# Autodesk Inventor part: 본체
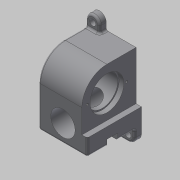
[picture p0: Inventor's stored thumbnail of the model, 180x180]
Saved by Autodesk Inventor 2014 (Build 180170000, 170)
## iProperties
Created: 2019-06
Part Number: 본체
Material: 알루미늄 6061
Document SubType Name: Modeling
Designer: mduedu
Density: 1 g/cm^3
Appearance: 기본값
Author: mduedu
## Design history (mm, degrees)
sketch "스케치1"
  geometry: L1 (37, 0)-(37, -43); L2 (37, -43)-(-60, -43); L3 (-60, -43)-(-60, 37); L4 (-60, 37)-(0, 37); A1 r 37 centre (0, 0) between (37, 0) and (0, 37); 1 further point
  constraints: 8 end point, 2 point on circle, 2 tangent, 1 centre point, 1 coincident, 1 horizontal, 1 parallel, 1 perpendicular, 1 vertical
  dimensions: "d0" = 37 radius of A1; "d2" = 80 distance of L2.end L3.end; "d3" = 97 distance of L1.end L2.end
extrude "돌출1" new body sketch "스케치1" stored distance "d4" = 72; taper "d5" = 0 deg
sketch "스케치2"
  geometry: L1 (72, 25)-(64, 25); L2 (64, 25)-(64, 97); L3 (64, 97)-(72, 97); L4 (72, 97)-(72, 25); L5 (72, 97)-(0, 97) reference; L6 (72, 60)-(72, 0) reference; 1 further point
  constraints: 8 end point, 2 collinear, 2 parallel, 1 horizontal, 1 perpendicular
  dimensions: "d6" = 72 distance between parallel lines of L1 L3; "d8" = 8 distance of L1.start L1.end
extrude "돌출2" cut sketch "스케치2" stored distance "d9" = 72; taper "d10" = 0 deg
sketch "스케치3"
  geometry: L1 (-36, -60)-(-36, 37) reference; L2 (-36, 37)-(28, 37) reference; L3 (28, 37)-(28, -35) reference; L4 (28, -35)-(36, -35) reference; L5 (36, -35)-(36, -60) reference; L6 (36, -60)-(-36, -60) reference; L7 (-36, 0)-(-19, 0); L8 (-19, 0)-(-19, 17.5); L9 (-19, 17.5)-(-36, 17.5); L10 (-36, 17.5)-(-36, 0); L11 (-19, 0)-(21, 0); L12 (21, 0)-(21, 23); L13 (21, 23)-(-19, 23); L14 (-19, 23)-(-19, 0); L15 (21, 0)-(28, 0); L16 (28, 0)-(28, 25); L17 (28, 25)-(21, 25); L18 (21, 25)-(21, 0); 1 further point
  constraints: 24 end point, 6 parallel, 3 horizontal, 3 perpendicular, 2 point on line, 1 horizontal alignment
  dimensions: "d11" = 7 distance of L16.end L17.end; "d13" = 47 distance between parallel lines of L3 L8; "d14" = 50 diameter of L17 L15; "d15" = 46 diameter of L13 L11; "d16" = 35 diameter of L9 L7
revolve "회전1" sketch "스케치3" stored, may be unused: angle "d17" = 90 deg
sketch "스케치4"
  geometry: C1 r 28 at (0, 0); 1 further point
  constraints: 1 centre point, 1 coincident
  dimensions: "d18" = 56 diameter of C1
extrude "돌출3" cut sketch "스케치4" distance "d19" = 2; taper "d20" = 0 deg
fillet "모깎기1" dims "d21" = 3
sketch "스케치5"
  geometry: C1 r 18 at (36, 26); 1 further point
  constraints: 1 centre point, 1 vertical alignment
  dimensions: "d22" = 36 diameter of C1; "d23" = 34 distance of C1.centre point (36, 60)
extrude "돌출4" cut sketch "스케치5" stored distance "d24" = 2; taper "d25" = 0 deg
sketch "스케치6"
  geometry: L1 (-37, -60)-(43, -60) reference; L2 (-8, -60)-(8, -60); L3 (8, -60)-(8, -51); L4 (8, -51)-(-8, -51); L5 (-8, -51)-(-8, -60); 2 further points
  constraints: 8 end point, 2 parallel, 1 horizontal, 1 midpoint, 1 perpendicular, 1 point on line, 1 vertical alignment
  dimensions: "d26" = 16 distance between parallel lines of L3 L5; "d28" = 9 distance between parallel lines of L1 L4
extrude "돌출5" cut sketch "스케치6" stored distance "d29" = 2; taper "d30" = 0 deg
sketch "스케치7"
  geometry: L1 (-10, -60)-(10, -60); L2 (10, -60)-(10, -48.967); L3 (10, -48.967)-(-10, -48.967); L4 (-10, -48.967)-(-10, -60); L5 (36, -60)-(-36, -60) reference; 3 further points
  constraints: 8 end point, 2 parallel, 1 collinear, 1 horizontal, 1 midpoint, 1 perpendicular, 1 vertical alignment, 2 other
  dimensions: "d31" = 20 distance of L2.end L3.end
extrude "돌출6" cut sketch "스케치7" stored distance "d33" = 2; taper "d34" = 0 deg
sketch "스케치8"
  geometry: L1 (0, 25)-(8, 25) reference; L2 (8, 25)-(8, 60) reference; L3 (72, 60)-(8, 60) reference; L4 (72, 0)-(72, 60) reference; L5 (72, 0)-(0, 0) reference; L6 (0, 25)-(0, 0) reference; L7 (72, 0)-(0, 0); L8 (0, 0)-(0, -20); L9 (0, -20)-(72, -20); L10 (72, -20)-(72, 0); C1 r 18 at (36, 26) reference; 1 further point
  constraints: 8 end point, 2 parallel, 1 horizontal, 1 perpendicular, 1 point on line
  dimensions: "d35" = 20 distance of L7.end L8.end
extrude "돌출7" join sketch "스케치8" distance "d37" = 10; taper "d38" = 0 deg
sketch "스케치9"
  geometry: L1 (0, -37)-(0, 0) reference; L2 (0, 0)-(64, 0) reference; L3 (64, -37)-(64, 0) reference; L4 (44, 0)-(64, 0); L5 (64, 0)-(64, 20); L6 (64, 20)-(44, 20); L7 (44, 20)-(44, 0); 1 further point
  constraints: 9 end point, 2 perpendicular, 1 horizontal, 1 parallel
  dimensions: "d39" = 20 distance of L2.end L5.end; "d51" = 20 distance of L5.end L6.end
extrude "돌출8" join sketch "스케치9" distance "d41" = 10; taper "d42" = 0 deg
fillet "모깎기2" dims "d43" = 10
sketch "스케치10"
  geometry: L1 (-62, -20)-(-10, -20) reference; L2 (0, -10)-(0, 0) reference; L3 (-72, 0)-(0, 0) reference; L4 (-72, 0)-(-72, -10) reference; C1 r 4.5 at (-62, -10); C2 r 4.5 at (-10, -10); A1 r 10 centre (-62, -10) between (-72, -10) and (-62, -20) reference; A2 r 10 centre (-10, -10) between (-10, -20) and (0, -10) reference; 1 further point
  constraints: 2 centre point, 2 coincident, 1 equal radius
  dimensions: "d44" = 9 diameter of C1
extrude "돌출9" cut sketch "스케치10" stored distance "d45" = 10; taper "d46" = 0 deg
sketch "스케치11"
  geometry: L1 (-64, 10)-(-64, 0) reference; L2 (-44, 0)-(-64, 0) reference; L3 (-44, 0)-(-44, 10) reference; C1 r 4.5 at (-54, 10); A1 r 10 centre (-54, 10) between (-44, 10) and (-64, 10) reference; 1 further point
  constraints: 1 centre point, 1 coincident
  dimensions: "d47" = 9 diameter of C1
extrude "돌출10" cut sketch "스케치11" stored distance "d48" = 10; taper "d49" = 0 deg
fillet "모깎기4" dims "d52" = 3
fillet "모깎기5" dims "d53" = 3
fillet "모깎기6" dims "d54" = 3
fillet "모깎기7" dims "d55" = 3
sketch "스케치12" dims "d56" = 58
  geometry: 3 further points
  constraints: 2 horizontal alignment, 1 coincident, 2 other
hole "구멍1" sketch "스케치12" at (66, 35) diameter "d57" = 3.242; stored, may be unused: countersink angle "d61" = 90 deg, drill point angle "d63" = 118 deg; dims "d58" = 10, "d59" = 4, "d60" = 2, "d62" = 12
sketch "스케치13" dims "d67" = 44
  geometry: 3 further points
  constraints: 2 vertical alignment, 1 coincident, 2 other
hole "구멍2" sketch "스케치13" at (0, 22) diameter "d68" = 3.242; stored, may be unused: countersink angle "d72" = 90 deg, drill point angle "d74" = 118 deg; dims "d69" = 10, "d70" = 4, "d71" = 2, "d73" = 12
sketch "스케치14"
  geometry: 3 further points
  constraints: 2 horizontal alignment
  dimensions: "d78" = 25 distance of point (11, 8) point (36, 8); "d79" = 25 distance of point (61, 8) point (36, 8)
hole "구멍3" sketch "스케치14" at (11, 8), (61, 8) diameter "d80" = 3.242; stored, may be unused: countersink angle "d84" = 90 deg, drill point angle "d86" = 118 deg; dims "d81" = 8, "d82" = 4, "d83" = 2, "d85" = 10
node "솔리드1"
pattern_circular "원형 패턴1" dims angle "d65" = 360 deg
pattern_circular "원형 패턴2" dims angle "d76" = 360 deg
node "투영된 루프1"
node "투영된 루프2"
node "투영된 루프3"
node "절단 모서리 투영1"
